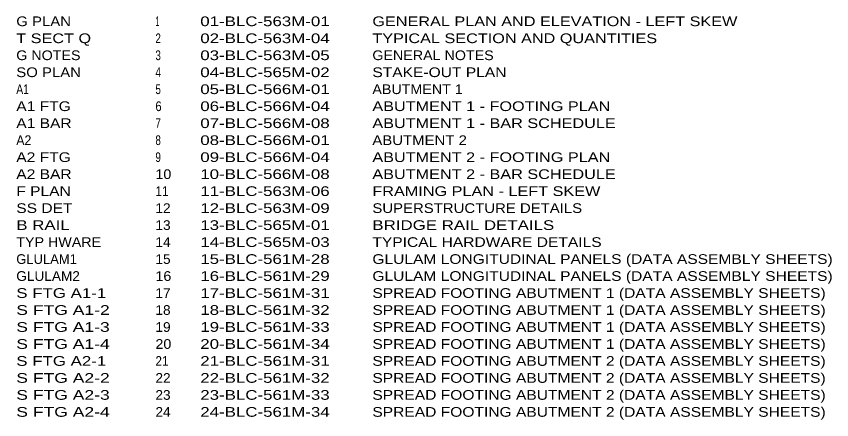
# Model space of a CAD drawing. Extents: x 179 to 461, y -288 to 18.
# Drawn here: x 218.6 to 454.9, y -288.3 to -171.4 of the extents above; entities that cross this region are included whole.
import ezdxf

# ---------------------------------------------------------------- set-up
doc = ezdxf.new("R2010")
doc.units = 0
doc.header["$LTSCALE"] = 0.048
doc.layers.add('62', color=7, linetype='Continuous')

msp = doc.modelspace()

# ---------------------------------------------------------------- texts
at = {"layer": '62'}
for s, width, p in [('G PLAN', 1.15, (218.61233, -174.29392)), ('1', 0.45, (258.94525, -174.29392)), ('01-BLC-563M-01', 1.3, (271.93967, -174.29392)), ('GENERAL PLAN AND ELEVATION - LEFT SKEW', 1.25, (321.81008, -174.29392)), ('T SECT Q', 1.25, (218.61233, -179.21583)), ('2', 0.75, (258.94525, -179.21583)), ('02-BLC-563M-04', 1.3, (271.93967, -179.21583)), ('TYPICAL SECTION AND QUANTITIES', 1.25, (321.81008, -179.21583)), ('G NOTES', 1.1, (218.61233, -184.13775)), ('3', 0.75, (258.94525, -184.13775)), ('03-BLC-563M-05', 1.3, (271.93967, -184.13775)), ('GENERAL NOTES', 1.1, (321.81008, -184.13775)), ('SO PLAN', 1.15, (218.61233, -189.05967)), ('4', 0.75, (258.94525, -189.05967)), ('04-BLC-565M-02', 1.3, (271.93967, -189.05967)), ('STAKE-OUT PLAN', 1.2, (321.81008, -189.05967)), ('A1', 0.8, (218.61233, -193.98158)), ('5', 0.75, (258.94525, -193.98158)), ('05-BLC-566M-01', 1.3, (271.93967, -193.98158)), ('ABUTMENT 1', 1.1, (321.81008, -193.98158)), ('A1 FTG', 1.2, (218.61233, -198.9035)), ('6', 0.85, (258.94525, -198.9035)), ('06-BLC-566M-04', 1.3, (271.93967, -198.9035)), ('ABUTMENT 1 - FOOTING PLAN', 1.25, (321.81008, -198.9035)), ('A1 BAR', 1.2, (218.61233, -203.82542)), ('7', 0.75, (258.94525, -203.82542)), ('07-BLC-566M-08', 1.3, (271.93967, -203.82542)), ('ABUTMENT 1 - BAR SCHEDULE', 1.25, (321.81008, -203.82542)), ('A2', 0.95, (218.61233, -208.74733)), ('8', 0.75, (258.94525, -208.74733)), ('08-BLC-566M-01', 1.3, (271.93967, -208.74733)), ('ABUTMENT 2', 1.15, (321.81008, -208.74733)), ('A2 FTG', 1.2, (218.61233, -213.66925)), ('9', 0.75, (258.94525, -213.66925)), ('09-BLC-566M-04', 1.3, (271.93967, -213.66925)), ('ABUTMENT 2 - FOOTING PLAN', 1.25, (321.81008, -213.66925)), ('A2 BAR', 1.2, (218.61233, -218.59117)), ('10', 1.1, (258.94525, -218.59117)), ('10-BLC-566M-08', 1.3, (271.93967, -218.59117)), ('ABUTMENT 2 - BAR SCHEDULE', 1.25, (321.81008, -218.59117)), ('F PLAN', 1.2, (218.61233, -223.51308)), ('11', 0.9, (258.94525, -223.51308)), ('11-BLC-563M-06', 1.3, (271.93967, -223.51308)), ('FRAMING PLAN - LEFT SKEW', 1.25, (321.81008, -223.51308)), ('SS DET', 1.2, (218.61233, -228.435)), ('12', 1.05, (258.94525, -228.435)), ('12-BLC-563M-09', 1.3, (271.93967, -228.435)), ('SUPERSTRUCTURE DETAILS', 1.15, (321.81008, -228.435)), ('B RAIL', 1.3, (218.61233, -233.35692)), ('13', 1.05, (258.94525, -233.35692)), ('13-BLC-565M-01', 1.3, (271.93967, -233.35692)), ('BRIDGE RAIL DETAILS', 1.3, (321.81008, -233.35692)), ('TYP HWARE', 1.1, (218.61233, -238.27883)), ('14', 1.05, (258.94525, -238.27883)), ('14-BLC-565M-03', 1.3, (271.93967, -238.27883)), ('TYPICAL HARDWARE DETAILS', 1.2, (321.81008, -238.27883)), ('15', 1.05, (258.94525, -243.20075)), ('15-BLC-561M-28', 1.3, (271.93967, -243.20075)), ('GLULAM LONGITUDINAL PANELS (DATA ASSEMBLY SHEETS)', 1.2, (321.81008, -243.20075)), ('GLULAM2', 1.05, (218.61233, -248.12267)), ('16', 1.1, (258.94525, -248.12267)), ('16-BLC-561M-29', 1.3, (271.93967, -248.12267)), ('GLULAM LONGITUDINAL PANELS (DATA ASSEMBLY SHEETS)', 1.2, (321.81008, -248.12267)), ('S FTG A1-1', 1.3, (218.61233, -253.04458)), ('17', 1.05, (258.94525, -253.04458)), ('17-BLC-561M-31', 1.3, (271.93967, -253.04458)), ('SPREAD FOOTING ABUTMENT 1 (DATA ASSEMBLY SHEETS)', 1.2, (321.81008, -253.04458)), ('S FTG A1-2', 1.35, (218.61233, -257.9665)), ('18', 1.05, (258.94525, -257.9665)), ('18-BLC-561M-32', 1.3, (271.93967, -257.9665)), ('SPREAD FOOTING ABUTMENT 1 (DATA ASSEMBLY SHEETS)', 1.2, (321.81008, -257.9665)), ('SPREAD FOOTING ABUTMENT 1 (DATA ASSEMBLY SHEETS)', 1.2, (321.81008, -262.88842)), ('S FTG A1-3', 1.35, (218.61233, -262.88842)), ('19', 1.05, (258.94525, -262.88842)), ('19-BLC-561M-33', 1.3, (271.93967, -262.88842)), ('S FTG A1-4', 1.35, (218.61233, -267.81033)), ('20', 1.1, (258.94525, -267.81033)), ('20-BLC-561M-34', 1.3, (271.93967, -267.81033)), ('SPREAD FOOTING ABUTMENT 1 (DATA ASSEMBLY SHEETS)', 1.2, (321.81008, -267.81033)), ('S FTG A2-1', 1.3, (218.61233, -272.73225)), ('21', 0.9, (258.94525, -272.73225)), ('21-BLC-561M-31', 1.3, (271.93967, -272.73225)), ('SPREAD FOOTING ABUTMENT 2 (DATA ASSEMBLY SHEETS)', 1.2, (321.81008, -272.73225)), ('S FTG A2-2', 1.35, (218.61233, -277.65417)), ('22', 1.05, (258.94525, -277.65417)), ('22-BLC-561M-32', 1.3, (271.93967, -277.65417)), ('SPREAD FOOTING ABUTMENT 2 (DATA ASSEMBLY SHEETS)', 1.2, (321.81008, -277.65417)), ('S FTG A2-3', 1.35, (218.61233, -282.57608)), ('23', 1.05, (258.94525, -282.57608)), ('23-BLC-561M-33', 1.3, (271.93967, -282.57608)), ('SPREAD FOOTING ABUTMENT 2 (DATA ASSEMBLY SHEETS)', 1.2, (321.81008, -282.57608)), ('S FTG A2-4', 1.35, (218.61233, -287.498)), ('24', 1.05, (258.94525, -287.498)), ('24-BLC-561M-34', 1.3, (271.93967, -287.498)), ('SPREAD FOOTING ABUTMENT 2 (DATA ASSEMBLY SHEETS)', 1.2, (321.81008, -287.498))]:
    msp.add_text(s, height=2.812, dxfattribs=dict(at, width=width)).set_placement(p)
msp.add_text('GLULAM1', height=2.812, dxfattribs=at).set_placement((218.61233, -243.20075))

doc.saveas('drawing.dxf')
